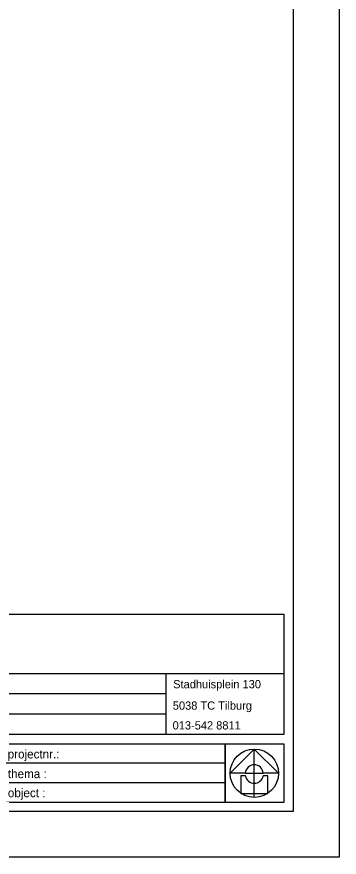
# Model space of a CAD drawing. Extents: x 133869.4 to 133911.4, y 396603.2 to 396662.6.
# Drawn here: x 133897.36 to 133911.41, y 396603.18 to 396639.82 of the extents above; entities that cross this region are included whole.
import ezdxf

# ---------------------------------------------------------------- set-up
doc = ezdxf.new("R2010")
doc.units = 0
for name, color, linetype in [('Ak-nrdp-noordpijl', 7, 'Continuous'), ('Ak-rand-kaderrand', 7, 'Continuous'), ('Ak-stpl-tekeninghoofd', 7, 'Continuous')]:
    doc.layers.add(name, color=color, linetype=linetype)

msp = doc.modelspace()

# ---------------------------------------------------------------- linework, layer by layer
at = {"layer": 'Ak-nrdp-noordpijl'}
for p, q in [((133906.66, 396606.839), (133907.714, 396607.893)), ((133907.714, 396605.786), (133907.714, 396607.893)), ((133907.714, 396607.893), (133908.768, 396606.84)), ((133907.32, 396606.839), (133906.66, 396606.839)), ((133907.32, 396606.839), (133908.101, 396606.839)), ((133908.768, 396606.839), (133908.101, 396606.839))]:
    msp.add_line(p, q, dxfattribs=at)
for points in [[(133907.328, 396606.722), (133907.131, 396606.722), (133907.131, 396605.962)], [(133908.297, 396605.962), (133908.297, 396606.722), (133908.1, 396606.722)], [(133907.131, 396605.962), (133908.297, 396605.962)]]:
    msp.add_lwpolyline(points, dxfattribs=at)
msp.add_circle((133907.714, 396606.84), 1.054, dxfattribs=at)
for centre, major_axis, start_param, end_param in [((133907.711, 396606.808), (0, 0.405), 4.79025, 7.776121), ((133907.711, 396606.808), (0, 0.405), 1.784473, 3.150166), ((133907.717, 396606.808), (0, -0.405), 6.274612, 7.640305)]:
    msp.add_ellipse(centre, major_axis=major_axis, ratio=0.966845, start_param=start_param, end_param=end_param, dxfattribs=at)
at = {"layer": 'Ak-rand-kaderrand'}
msp.add_lwpolyline([(133911.415, 396662.579), (133911.415, 396603.179), (133869.415, 396603.179), (133869.415, 396662.579)], close=True, dxfattribs=at)
msp.add_lwpolyline([(133909.415, 396660.579), (133871.57, 396660.579), (133871.57, 396605.179), (133909.415, 396605.179), (133909.415, 396660.579)], dxfattribs=at)
at = {"layer": 'Ak-stpl-tekeninghoofd'}
for p, q in [((133908.997, 396611.179), (133885.278, 396611.179)), ((133903.875, 396608.523), (133903.875, 396611.179)), ((133903.875, 396610.299), (133885.278, 396610.299)), ((133903.875, 396609.411), (133885.278, 396609.411)), ((133906.441, 396607.275), (133873.683, 396607.275)), ((133906.441, 396606.423), (133873.683, 396606.423))]:
    msp.add_line(p, q, dxfattribs=at)
for points in [[(133873.682, 396613.776), (133908.997, 396613.776), (133908.997, 396608.523), (133873.682, 396608.523)], [(133873.683, 396608.127), (133906.441, 396608.127), (133906.441, 396605.57), (133873.683, 396605.57)], [(133906.441, 396608.127), (133908.998, 396608.127), (133908.998, 396605.57), (133906.441, 396605.57)]]:
    msp.add_lwpolyline(points, close=True, dxfattribs=at)

# ---------------------------------------------------------------- texts
for s, height, p in [('Stadhuisplein 130', 0.36, (133904.177, 396610.543)), ('5038 TC Tilburg', 0.36, (133904.16, 396609.61)), ('013-542 8811', 0.36, (133904.151, 396608.747)), ('projectnr.:', 0.38, (133896.959, 396607.485)), ('thema :', 0.38, (133896.968, 396606.626)), ('object :', 0.38, (133896.968, 396605.794))]:
    msp.add_text(s, height=height, dxfattribs=at).set_placement(p)

doc.saveas('drawing.dxf')
